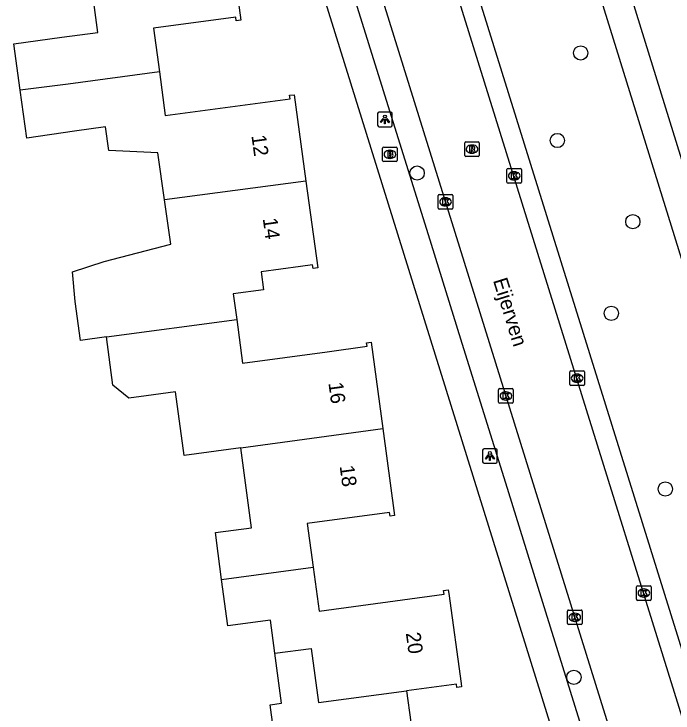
# Model space of a CAD drawing. Extents: x 163427 to 164190, y 380331 to 381641.
# Drawn here: x 163655.33 to 163700.44, y 381010.31 to 381058.15 of the extents above; entities that cross this region are included whole.
import ezdxf

# ---------------------------------------------------------------- set-up
doc = ezdxf.new("R2010")
doc.units = 0
for name, color, linetype in [('IMGEO_Boom', 7, 'Continuous'), ('IMGEO_Brandkraan', 7, 'Continuous'), ('IMGEO_Kolk', 7, 'Continuous'), ('IMGEO_Lichtpunt', 7, 'Continuous'), ('IMGEO_Openbare_ruimte_label', 7, 'Continuous'), ('IMGEO_Pand', 7, 'Continuous'), ('IMGEO_Pand_nummerreeks', 7, 'Continuous'), ('IMGEO_Rijbaan_lokaal_open', 7, 'Continuous'), ('IMGEO_Rioolput', 7, 'Continuous'), ('IMGEO_Voetpad_halfverhard', 7, 'Continuous'), ('IMGEO_Voetpad_open', 7, 'Continuous')]:
    doc.layers.add(name, color=color, linetype=linetype)

msp = doc.modelspace()

# ---------------------------------------------------------------- linework, layer by layer
at = {"layer": 'IMGEO_Boom'}
for centre in [(163694.123, 381055.483), (163692.528, 381049.491), (163682.926, 381047.262), (163697.692, 381043.937), (163696.22, 381037.667), (163699.914, 381025.641), (163693.659, 381012.758)]:
    msp.add_circle(centre, 0.489, dxfattribs=at)
at = {"layer": 'IMGEO_Brandkraan'}
for p, q in [((163680.568, 381048.119), (163680.568, 381048.971)), ((163680.643, 381049.045), (163681.495, 381049.045)), ((163681.569, 381048.971), (163681.569, 381048.119)), ((163681.056, 381048.825), (163681.081, 381048.825)), ((163681.495, 381048.045), (163680.643, 381048.045)), ((163681.079, 381048.265), (163681.054, 381048.265))]:
    msp.add_line(p, q, dxfattribs=at)
for points in [[(163680.568, 381048.119), (163680.568, 381048.971)], [(163680.643, 381049.045), (163681.495, 381049.045)], [(163681.569, 381048.971), (163681.569, 381048.119)], [(163680.916, 381048.745), (163680.916, 381048.345), (163681.129, 381048.345)], [(163681.147, 381048.745), (163680.916, 381048.745)], [(163681.095, 381048.664), (163681.041, 381048.664), (163681.041, 381048.588)], [(163681.041, 381048.588), (163681.094, 381048.588)], [(163681.103, 381048.512), (163681.041, 381048.512), (163681.041, 381048.431)], [(163681.495, 381048.045), (163680.643, 381048.045)], [(163681.041, 381048.431), (163681.103, 381048.431)]]:
    msp.add_lwpolyline(points, dxfattribs=at)
for centre, radius, start, end in [((163680.645, 381048.969), 0.0765, 91.552, 178.448), ((163680.645, 381048.969), 0.0765, 91.552, 178.448), ((163681.493, 381048.969), 0.0765, 1.552, 88.448), ((163681.493, 381048.969), 0.0765, 1.552, 88.448), ((163681.096, 381048.626), 0.0379, 267.8285, 90.9355), ((163681.104, 381048.471), 0.0404, 269.8759, 90.5077), ((163681.151, 381048.6), 0.145, 59.4692, 91.5367), ((163681.176, 381048.647), 0.0922, 285.5137, 58.1501), ((163681.181, 381048.455), 0.105, 301.3115, 78.989), ((163680.645, 381048.121), 0.0765, 181.552, 268.448), ((163680.645, 381048.121), 0.0765, 181.552, 268.448), ((163681.135, 381048.596), 0.251, 268.6676, 293.5347), ((163681.493, 381048.121), 0.0765, 271.552, 358.448), ((163681.493, 381048.121), 0.0765, 271.552, 358.448)]:
    msp.add_arc(centre, radius, start, end, dxfattribs=at)
for centre, major_axis, ratio, start_param, end_param in [((163681.055, 381048.545), (-0.387, 0.002), 0.722429, 4.712389, 7.853982), ((163681.08, 381048.545), (-0.39, 0.002), 0.717154, 1.570796, 4.712389)]:
    msp.add_ellipse(centre, major_axis=major_axis, ratio=ratio, start_param=start_param, end_param=end_param, dxfattribs=at)
at = {"layer": 'IMGEO_Kolk'}
for p, q in [((163689.075, 381046.645), (163689.075, 381047.497)), ((163689.15, 381047.571), (163690.002, 381047.571)), ((163690.076, 381047.497), (163690.076, 381046.645)), ((163689.563, 381047.351), (163689.588, 381047.351)), ((163690.002, 381046.571), (163689.15, 381046.571)), ((163689.586, 381046.791), (163689.561, 381046.791)), ((163684.372, 381044.866), (163684.372, 381045.718)), ((163684.447, 381045.792), (163685.299, 381045.792)), ((163685.373, 381045.718), (163685.373, 381044.866)), ((163684.86, 381045.572), (163684.885, 381045.572)), ((163685.299, 381044.792), (163684.447, 381044.792)), ((163684.883, 381045.012), (163684.858, 381045.012)), ((163693.38, 381032.798), (163693.38, 381033.65)), ((163693.455, 381033.724), (163694.307, 381033.724)), ((163694.381, 381033.65), (163694.381, 381032.798)), ((163693.868, 381033.504), (163693.893, 381033.504)), ((163694.307, 381032.724), (163693.455, 381032.724)), ((163693.891, 381032.944), (163693.866, 381032.944)), ((163688.506, 381031.585), (163688.506, 381032.437)), ((163688.581, 381032.511), (163689.433, 381032.511)), ((163688.994, 381032.291), (163689.019, 381032.291)), ((163689.507, 381032.437), (163689.507, 381031.585)), ((163689.017, 381031.731), (163688.992, 381031.731)), ((163689.433, 381031.511), (163688.581, 381031.511)), ((163697.949, 381018.099), (163697.949, 381018.951)), ((163698.024, 381019.025), (163698.876, 381019.025)), ((163698.437, 381018.805), (163698.462, 381018.805)), ((163698.95, 381018.951), (163698.95, 381018.099)), ((163698.876, 381018.025), (163698.024, 381018.025)), ((163698.46, 381018.245), (163698.435, 381018.245)), ((163693.295, 381017.363), (163694.147, 381017.363)), ((163693.22, 381016.437), (163693.22, 381017.289)), ((163693.708, 381017.143), (163693.733, 381017.143)), ((163694.221, 381017.289), (163694.221, 381016.437)), ((163693.731, 381016.583), (163693.706, 381016.583)), ((163694.147, 381016.363), (163693.295, 381016.363))]:
    msp.add_line(p, q, dxfattribs=at)
for points in [[(163689.075, 381046.645), (163689.075, 381047.497)], [(163689.15, 381047.571), (163690.002, 381047.571)], [(163690.076, 381047.497), (163690.076, 381046.645)], [(163689.396, 381047.271), (163689.519, 381047.271), (163689.519, 381047.12), (163689.649, 381047.271), (163689.813, 381047.271), (163689.667, 381047.12), (163689.82, 381046.871), (163689.668, 381046.871), (163689.583, 381047.035), (163689.519, 381046.968), (163689.519, 381046.871), (163689.396, 381046.871), (163689.396, 381047.271)], [(163690.002, 381046.571), (163689.15, 381046.571)], [(163684.372, 381044.866), (163684.372, 381045.718)], [(163684.447, 381045.792), (163685.299, 381045.792)], [(163685.373, 381045.718), (163685.373, 381044.866)], [(163684.693, 381045.492), (163684.816, 381045.492), (163684.816, 381045.341), (163684.946, 381045.492), (163685.11, 381045.492), (163684.964, 381045.341), (163685.117, 381045.092), (163684.965, 381045.092), (163684.88, 381045.256), (163684.816, 381045.189), (163684.816, 381045.092), (163684.693, 381045.092), (163684.693, 381045.492)], [(163685.299, 381044.792), (163684.447, 381044.792)], [(163693.38, 381032.798), (163693.38, 381033.65)], [(163693.455, 381033.724), (163694.307, 381033.724)], [(163694.381, 381033.65), (163694.381, 381032.798)], [(163693.701, 381033.424), (163693.824, 381033.424), (163693.824, 381033.273), (163693.954, 381033.424), (163694.118, 381033.424), (163693.972, 381033.273), (163694.125, 381033.024), (163693.973, 381033.024), (163693.888, 381033.188), (163693.824, 381033.121), (163693.824, 381033.024), (163693.701, 381033.024), (163693.701, 381033.424)], [(163694.307, 381032.724), (163693.455, 381032.724)], [(163688.506, 381031.585), (163688.506, 381032.437)], [(163688.581, 381032.511), (163689.433, 381032.511)], [(163688.827, 381032.211), (163688.95, 381032.211), (163688.95, 381032.06), (163689.08, 381032.211), (163689.244, 381032.211), (163689.098, 381032.06), (163689.251, 381031.811), (163689.099, 381031.811), (163689.014, 381031.975), (163688.95, 381031.908), (163688.95, 381031.811), (163688.827, 381031.811), (163688.827, 381032.211)], [(163689.507, 381032.437), (163689.507, 381031.585)], [(163689.433, 381031.511), (163688.581, 381031.511)], [(163697.949, 381018.099), (163697.949, 381018.951)], [(163698.024, 381019.025), (163698.876, 381019.025)], [(163698.95, 381018.951), (163698.95, 381018.099)], [(163698.27, 381018.725), (163698.393, 381018.725), (163698.393, 381018.574), (163698.523, 381018.725), (163698.687, 381018.725), (163698.541, 381018.574), (163698.694, 381018.325), (163698.542, 381018.325), (163698.457, 381018.489), (163698.393, 381018.422), (163698.393, 381018.325), (163698.27, 381018.325), (163698.27, 381018.725)], [(163698.876, 381018.025), (163698.024, 381018.025)], [(163693.295, 381017.363), (163694.147, 381017.363)], [(163693.22, 381016.437), (163693.22, 381017.289)], [(163693.541, 381017.063), (163693.664, 381017.063), (163693.664, 381016.912), (163693.794, 381017.063), (163693.958, 381017.063), (163693.812, 381016.912), (163693.965, 381016.663), (163693.813, 381016.663), (163693.728, 381016.827), (163693.664, 381016.76), (163693.664, 381016.663), (163693.541, 381016.663), (163693.541, 381017.063)], [(163694.221, 381017.289), (163694.221, 381016.437)], [(163694.147, 381016.363), (163693.295, 381016.363)]]:
    msp.add_lwpolyline(points, dxfattribs=at)
for centre, start, end in [((163689.152, 381047.495), 91.552, 178.448), ((163689.152, 381047.495), 91.552, 178.448), ((163690, 381047.495), 1.552, 88.448), ((163690, 381047.495), 1.552, 88.448), ((163689.152, 381046.647), 181.552, 268.448), ((163689.152, 381046.647), 181.552, 268.448), ((163690, 381046.647), 271.552, 358.448), ((163690, 381046.647), 271.552, 358.448), ((163684.449, 381045.716), 91.552, 178.448), ((163684.449, 381045.716), 91.552, 178.448), ((163685.297, 381045.716), 1.552, 88.448), ((163685.297, 381045.716), 1.552, 88.448), ((163684.449, 381044.868), 181.552, 268.448), ((163684.449, 381044.868), 181.552, 268.448), ((163685.297, 381044.868), 271.552, 358.448), ((163685.297, 381044.868), 271.552, 358.448), ((163693.457, 381033.648), 91.552, 178.448), ((163693.457, 381033.648), 91.552, 178.448), ((163694.305, 381033.648), 1.552, 88.448), ((163694.305, 381033.648), 1.552, 88.448), ((163693.457, 381032.8), 181.552, 268.448), ((163693.457, 381032.8), 181.552, 268.448), ((163694.305, 381032.8), 271.552, 358.448), ((163694.305, 381032.8), 271.552, 358.448), ((163688.583, 381032.435), 91.552, 178.448), ((163688.583, 381032.435), 91.552, 178.448), ((163689.431, 381032.435), 1.552, 88.448), ((163689.431, 381032.435), 1.552, 88.448), ((163688.583, 381031.587), 181.552, 268.448), ((163688.583, 381031.587), 181.552, 268.448), ((163689.431, 381031.587), 271.552, 358.448), ((163689.431, 381031.587), 271.552, 358.448), ((163698.026, 381018.949), 91.552, 178.448), ((163698.026, 381018.949), 91.552, 178.448), ((163698.874, 381018.949), 1.552, 88.448), ((163698.874, 381018.949), 1.552, 88.448), ((163698.026, 381018.101), 181.552, 268.448), ((163698.026, 381018.101), 181.552, 268.448), ((163698.874, 381018.101), 271.552, 358.448), ((163698.874, 381018.101), 271.552, 358.448), ((163693.297, 381017.287), 91.552, 178.448), ((163693.297, 381017.287), 91.552, 178.448), ((163694.145, 381017.287), 1.552, 88.448), ((163694.145, 381017.287), 1.552, 88.448), ((163693.297, 381016.439), 181.552, 268.448), ((163693.297, 381016.439), 181.552, 268.448), ((163694.145, 381016.439), 271.552, 358.448), ((163694.145, 381016.439), 271.552, 358.448)]:
    msp.add_arc(centre, 0.0765, start, end, dxfattribs=at)
for centre, major_axis, ratio, start_param, end_param in [((163689.562, 381047.071), (-0.387, 0.002), 0.722429, 4.712389, 7.853982), ((163689.587, 381047.071), (-0.39, 0.002), 0.717154, 1.570796, 4.712389), ((163684.859, 381045.292), (-0.387, 0.002), 0.722429, 4.712389, 7.853982), ((163684.884, 381045.292), (-0.39, 0.002), 0.717154, 1.570796, 4.712389), ((163693.867, 381033.224), (-0.387, 0.002), 0.722429, 4.712389, 7.853982), ((163693.892, 381033.224), (-0.39, 0.002), 0.717154, 1.570796, 4.712389), ((163688.993, 381032.011), (-0.387, 0.002), 0.722429, 4.712389, 7.853982), ((163689.018, 381032.011), (-0.39, 0.002), 0.717154, 1.570796, 4.712389), ((163698.436, 381018.525), (-0.387, 0.002), 0.722429, 4.712389, 7.853982), ((163698.461, 381018.525), (-0.39, 0.002), 0.717154, 1.570796, 4.712389), ((163693.707, 381016.863), (-0.387, 0.002), 0.722429, 4.712389, 7.853982), ((163693.732, 381016.863), (-0.39, 0.002), 0.717154, 1.570796, 4.712389)]:
    msp.add_ellipse(centre, major_axis=major_axis, ratio=ratio, start_param=start_param, end_param=end_param, dxfattribs=at)
at = {"layer": 'IMGEO_Lichtpunt'}
for p, q in [((163680.224, 381051.338), (163680.224, 381050.531)), ((163680.224, 381051.338), (163680.224, 381050.531)), ((163681.126, 381051.433), (163680.318, 381051.433)), ((163681.126, 381051.433), (163680.318, 381051.433)), ((163681.22, 381050.531), (163681.22, 381051.338)), ((163681.22, 381050.531), (163681.22, 381051.338)), ((163680.318, 381050.437), (163681.126, 381050.437)), ((163680.318, 381050.437), (163681.126, 381050.437)), ((163688.316, 381028.403), (163687.508, 381028.403)), ((163688.316, 381028.403), (163687.508, 381028.403)), ((163687.414, 381028.308), (163687.414, 381027.501)), ((163687.414, 381028.308), (163687.414, 381027.501)), ((163688.41, 381027.501), (163688.41, 381028.308)), ((163688.41, 381027.501), (163688.41, 381028.308)), ((163687.508, 381027.407), (163688.316, 381027.407)), ((163687.508, 381027.407), (163688.316, 381027.407))]:
    msp.add_line(p, q, dxfattribs=at)
for points in [[(163680.598, 381051.002), (163680.637, 381050.974), (163680.449, 381050.712), (163680.411, 381050.739), (163680.598, 381051.002)], [(163680.7, 381050.954), (163680.747, 381050.954), (163680.747, 381050.632), (163680.7, 381050.632), (163680.7, 381050.954)], [(163680.81, 381050.974), (163680.848, 381051.001), (163681.035, 381050.739), (163680.996, 381050.711), (163680.81, 381050.974)], [(163687.788, 381027.972), (163687.827, 381027.944), (163687.639, 381027.682), (163687.601, 381027.709), (163687.788, 381027.972)], [(163687.89, 381027.924), (163687.937, 381027.924), (163687.937, 381027.602), (163687.89, 381027.602), (163687.89, 381027.924)], [(163688, 381027.944), (163688.038, 381027.971), (163688.225, 381027.709), (163688.186, 381027.681), (163688, 381027.944)]]:
    msp.add_lwpolyline(points, dxfattribs=at)
for centre in [(163680.723, 381051.136), (163687.913, 381028.106)]:
    msp.add_circle(centre, 0.0994, dxfattribs=at)
for centre, start, end in [((163680.318, 381051.338), 90, 180), ((163680.318, 381051.338), 90, 180), ((163681.126, 381051.338), 0, 90), ((163681.126, 381051.338), 0, 90), ((163680.318, 381050.531), 180, 270), ((163680.318, 381050.531), 180, 270), ((163681.126, 381050.531), 270, 0), ((163681.126, 381050.531), 270, 360), ((163687.508, 381028.308), 90, 180), ((163687.508, 381028.308), 90, 180), ((163688.316, 381028.308), 0, 90), ((163688.316, 381028.308), 0, 90), ((163687.508, 381027.501), 180, 270), ((163687.508, 381027.501), 180, 270), ((163688.316, 381027.501), 270, 0), ((163688.316, 381027.501), 270, 360)]:
    msp.add_arc(centre, 0.0946, start, end, dxfattribs=at)
at = {"layer": 'IMGEO_Pand'}
for points in [[(163670.07, 381063.639), (163670.866, 381057.722), (163670.549, 381057.679), (163670.515, 381057.928), (163664.892, 381057.181), (163665.29, 381054.187)], [(163655.763, 381052.929), (163655.335, 381056.114), (163658.604, 381056.554), (163661.079, 381056.887), (163660.34, 381062.378)], [(163665.29, 381054.187), (163659.034, 381053.357), (163655.763, 381052.929)], [(163665.29, 381054.187), (163665.686, 381051.201), (163674.23, 381052.335), (163674.197, 381052.584), (163674.514, 381052.627), (163675.32, 381046.71)], [(163665.644, 381045.43), (163665.185, 381048.643), (163661.824, 381048.804), (163661.592, 381050.426), (163659.469, 381050.122), (163656.204, 381049.655), (163655.763, 381052.929)], [(163675.32, 381046.71), (163665.644, 381045.43)], [(163675.32, 381046.71), (163676.129, 381040.773), (163675.812, 381040.73), (163675.778, 381040.978), (163674.946, 381040.866), (163672.25, 381040.502), (163672.416, 381039.275), (163670.345, 381038.995), (163670.58, 381037.25)], [(163661.658, 381036.052), (163659.887, 381035.816), (163659.525, 381038.481), (163659.351, 381040.515), (163661.509, 381041.213), (163666.077, 381042.399), (163665.644, 381045.43)], [(163661.658, 381036.052), (163670.58, 381037.25)], [(163670.58, 381037.25), (163670.984, 381034.258), (163676.772, 381035.039), (163679.501, 381035.407), (163679.468, 381035.656), (163679.785, 381035.699), (163680.585, 381029.782)], [(163670.855, 381028.464), (163666.978, 381027.939), (163666.389, 381032.298), (163664.379, 381032.026), (163663.188, 381031.865), (163662.099, 381032.746), (163661.658, 381036.052)], [(163670.855, 381028.464), (163680.585, 381029.782)], [(163680.585, 381029.782), (163681.39, 381023.835), (163681.073, 381023.792), (163681.039, 381024.041), (163675.411, 381023.279), (163675.816, 381020.287)], [(163669.548, 381019.459), (163669.31, 381021.227), (163669.117, 381022.66), (163671.593, 381022.994), (163670.855, 381028.464)], [(163669.548, 381019.459), (163675.816, 381020.287)], [(163675.816, 381020.287), (163676.222, 381017.284), (163684.773, 381018.44), (163684.74, 381018.69), (163685.057, 381018.733), (163685.09, 381018.484), (163685.937, 381012.343), (163685.971, 381012.095), (163685.654, 381012.052), (163685.62, 381012.3), (163682.207, 381011.84)], [(163673.189, 381014.404), (163672.884, 381016.663), (163669.978, 381016.271), (163669.548, 381019.459)], [(163673.189, 381014.404), (163675.682, 381014.74), (163676.18, 381011.045), (163682.207, 381011.84)], [(163682.207, 381011.84), (163682.788, 381007.541), (163673.482, 381006.285), (163672.864, 381010.873), (163673.651, 381010.98), (163673.189, 381014.404)]]:
    msp.add_lwpolyline(points, dxfattribs=at)
at = {"layer": 'IMGEO_Rijbaan_lokaal_open'}
for points in [[(163666.463, 381104.446), (163697.932, 381003.337)], [(163704.827, 380997.973), (163704.595, 380998.718), (163704.196, 381000), (163676.032, 381090.444), (163672.05, 381103.345)]]:
    msp.add_lwpolyline(points, dxfattribs=at)
at = {"layer": 'IMGEO_Rioolput'}
for p, q in [((163686.259, 381049.402), (163687.111, 381049.402)), ((163686.184, 381048.476), (163686.184, 381049.328)), ((163686.672, 381049.182), (163686.697, 381049.182)), ((163687.185, 381049.328), (163687.185, 381048.476)), ((163686.695, 381048.622), (163686.67, 381048.622)), ((163687.111, 381048.402), (163686.259, 381048.402))]:
    msp.add_line(p, q, dxfattribs=at)
for points in [[(163686.259, 381049.402), (163687.111, 381049.402)], [(163686.184, 381048.476), (163686.184, 381049.328)], [(163686.773, 381049.1), (163686.521, 381049.102), (163686.521, 381048.702)], [(163686.699, 381049.021), (163686.645, 381049.021), (163686.645, 381048.94)], [(163686.645, 381048.94), (163686.697, 381048.94)], [(163687.185, 381049.328), (163687.185, 381048.476)], [(163686.521, 381048.702), (163686.645, 381048.702), (163686.645, 381048.864), (163686.656, 381048.864)], [(163686.703, 381048.835), (163686.774, 381048.702), (163686.914, 381048.702), (163686.849, 381048.828)], [(163687.111, 381048.402), (163686.259, 381048.402)]]:
    msp.add_lwpolyline(points, dxfattribs=at)
for centre, radius, start, end in [((163686.261, 381049.326), 0.0765, 91.552, 178.448), ((163686.261, 381049.326), 0.0765, 91.552, 178.448), ((163687.109, 381049.326), 0.0765, 1.552, 88.448), ((163687.109, 381049.326), 0.0765, 1.552, 88.448), ((163686.681, 381049.129), 0.19, 274.7715, 282.9687), ((163686.705, 381048.925), 0.0964, 77.0061, 93.1865), ((163686.719, 381048.982), 0.0378, 276.6634, 79.6772), ((163686.772, 381048.99), 0.109, 350.3612, 89.416), ((163686.77, 381048.99), 0.112, 277.5842, 350.9817), ((163686.261, 381048.478), 0.0765, 181.552, 268.448), ((163686.261, 381048.478), 0.0765, 181.552, 268.448), ((163686.655, 381048.811), 0.0533, 26.0293, 88.6989), ((163686.754, 381048.775), 0.108, 29.5134, 73.7905), ((163687.109, 381048.478), 0.0765, 271.552, 358.448), ((163687.109, 381048.478), 0.0765, 271.552, 358.448)]:
    msp.add_arc(centre, radius, start, end, dxfattribs=at)
for centre, major_axis, ratio, start_param, end_param in [((163686.671, 381048.902), (-0.387, 0.002), 0.722429, 4.712389, 7.853982), ((163686.696, 381048.902), (-0.39, 0.002), 0.717154, 1.570796, 4.712389)]:
    msp.add_ellipse(centre, major_axis=major_axis, ratio=ratio, start_param=start_param, end_param=end_param, dxfattribs=at)
at = {"layer": 'IMGEO_Voetpad_halfverhard'}
for points in [[(163687.012, 381093.435), (163709.377, 381021.24)], [(163707.46, 381020.674), (163685.068, 381092.846)]]:
    msp.add_lwpolyline(points, dxfattribs=at)
at = {"layer": 'IMGEO_Voetpad_open'}
for points in [[(163692.559, 381007.908), (163662.718, 381103.781)], [(163695.441, 381005.322), (163691.21, 381018.912), (163689.196, 381025.38), (163685.923, 381035.891), (163683.903, 381042.378), (163680.63, 381052.891), (163678.617, 381059.355), (163675.341, 381069.878), (163673.323, 381076.358), (163669.956, 381087.172), (163667.938, 381093.654), (163665.558, 381101.299)], [(163674.534, 381099.72), (163702.368, 381010.393)]]:
    msp.add_lwpolyline(points, dxfattribs=at)

# ---------------------------------------------------------------- texts
at = {"layer": 'IMGEO_Openbare_ruimte_label'}
msp.add_text('Eijerven', height=1, rotation=287.2754, dxfattribs=at).set_placement((163688.113, 381039.92))
at = {"layer": 'IMGEO_Pand_nummerreeks'}
for s, rotation, p in [('12', 277.7576, (163671.584, 381049.827)), ('14', 277.7583, (163672.36, 381044.145)), ('16', 277.7061, (163676.854, 381032.898)), ('18', 277.7044, (163677.623, 381027.212)), ('20', 277.8512, (163682.152, 381015.781))]:
    msp.add_text(s, height=1, rotation=rotation, dxfattribs=at).set_placement(p)

doc.saveas('drawing.dxf')
